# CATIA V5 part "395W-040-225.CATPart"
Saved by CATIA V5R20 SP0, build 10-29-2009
Part number: 395W-040-225
Source: Unknown
Property "ARTICLENO": "395W-040-225"
Property "B": "60"
Property "BOMINFO": "395W-040-225"
Property "D": "34"
Property "D1": "32"
Property "D2": "40"
Property "DES": "LIFTING PIN BMW  KG.3200 Ø32X175"
Property "E1": "63"
Property "L": "175"
Property "L1": "175"
Property "L2": "10"
Property "LINA": "395W-040-225"
Property "MAT": "CK45"
Property "MDW": "6400"
Property "ML": "3200"
Property "NB": "395W-040-225"
Property "NBSYN": "395W-040-225"
Property "NN": "395W"
Property "NT": "Lifting pin VDI 3366"
Property "S": "140"
Property "S1": "40"
Property "SUPPLIER": "CF"
Bounding box of the stored display mesh (mm): x 0 to 225, y -26 to 25, z -25 to 25
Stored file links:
  C:\Users\Utente\Desktop\3D files 395W\395W-040-225.CATPart
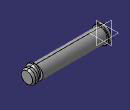
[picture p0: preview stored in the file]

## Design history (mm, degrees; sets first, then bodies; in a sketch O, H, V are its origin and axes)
Body1 "Geometry.1" (main body)
  Solid1 "395W-040-225.catpart": solid without history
